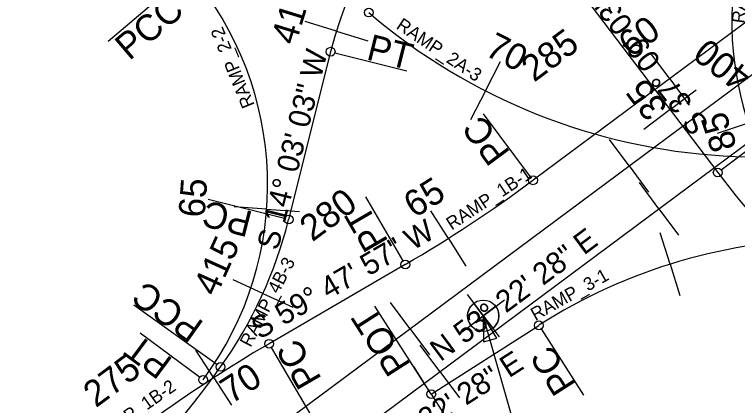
# Model space of a CAD drawing. Extents: x 1603447 to 1622636, y 1083818 to 1103958.
# Drawn here: x 1609242 to 1610566, y 1093148 to 1093865 of the extents above; entities that cross this region are included whole.
import ezdxf

# ---------------------------------------------------------------- set-up
doc = ezdxf.new("R2010")
doc.units = 0
for name, color, linetype in [('Level 1', 7, 'Continuous'), ('RD_HC_Points', 7, 'Continuous'), ('RD_HC_SUR_Bearing_TX400', 7, 'Continuous'), ('RD_HC_SUR_CL400', 7, 'Continuous'), ('RD_HC_SUR_PC_PT_400', 7, 'Continuous'), ('RD_HC_SUR_Tic400', 7, 'Continuous'), ('RD_HC_SUR_TX_Sta400', 7, 'Continuous'), ('RD_SHT_Misc1', 7, 'Continuous'), ('RD_TX_Misc1', 7, 'Continuous')]:
    doc.layers.add(name, color=color, linetype=linetype)

msp = doc.modelspace()

# ---------------------------------------------------------------- linework, layer by layer
at = {"layer": 'Level 1'}
for p, q in [((1609556.2, 1093936.7), (1609413.5, 1093815.2)), ((1609580.8, 1093200.1), (1609471.7, 1093281.1))]:
    msp.add_line(p, q, dxfattribs=at)
msp.add_circle((1609587.2, 1093195.4), 8, dxfattribs=at)
at = {"layer": 'RD_HC_Points'}
msp.add_lwpolyline([(1610156.3, 1093025.9), (1610177.4, 1093042.6), (1610100.4, 1093312.8)], dxfattribs=at)
msp.add_lwpolyline([(1610125.1, 1093271.6), (1610100.4, 1093312.8), (1610101.2, 1093264.8)], close=True, dxfattribs=at)
at = {"layer": 'RD_HC_SUR_CL400'}
for p, q in [((1609261, 1092765), (1614429, 1096606.7)), ((1611290.5, 1094378), (1610191.6, 1093561.1)), ((1610217, 1093988.4), (1610529.9, 1093575.5)), ((1609780.9, 1093032.2), (1610899.7, 1093863.9)), ((1609820.9, 1093796.8), (1609744, 1093489.3)), ((1609957.7, 1093406.8), (1609708.2, 1093261.6)), ((1610005.3, 1093169.1), (1610202.4, 1093295.3))]:
    msp.add_line(p, q, dxfattribs=at)
for centre, radius, start, end in [((1611155.6, 1093853.7), 600, 109.8521, 236.724), ((1610558.2, 1093612.3), 760, 18.4471, 165.9491), ((1608910.9, 1091669.6), 2932.1, 37.9336, 56.1301), ((1608910.9, 1091669.6), 2908.8, 39.6334, 56.1301), ((1609105.4, 1093553), 600, 323.4116, 40.4045), ((1610606.4, 1094704), 1100, 229.4294, 303.6278), ((1612124, 1094783.4), 2000, 217.1508, 224.9911), ((1608700.1, 1095567.5), 2500, 300.2008, 306.6256), ((1608967.9, 1093683.5), 800, 324.5024, 345.9491), ((1610741.6, 1092453.1), 1000, 90.0249, 122.6256), ((1610965.7, 1091100.9), 2500, 120.2008, 126.0872), ((1607990.9, 1094380.3), 2000, 306.4947, 324.5024)]:
    msp.add_arc(centre, radius, start, end, dxfattribs=at)
at = {"layer": 'RD_HC_SUR_PC_PT_400'}
for p, q in [((1609828.7, 1093794.8), (1609960.5, 1093761.9)), ((1610186.8, 1093567.5), (1610101, 1093682.9)), ((1610536.2, 1093580.4), (1610650.8, 1093667.2)), ((1609953.7, 1093413.7), (1609885.3, 1093531.1)), ((1609736.2, 1093491.2), (1609596.8, 1093526.1)), ((1609612.7, 1093223.6), (1609460.1, 1093332.5)), ((1610001, 1093175.8), (1609902.1, 1093330.3)), ((1610206.8, 1093288.6), (1610284.3, 1093167.5)), ((1609712.2, 1093254.7), (1609784.5, 1093130.4))]:
    msp.add_line(p, q, dxfattribs=at)
for centre in [(1609891, 1093868.4), (1609820.9, 1093796.8), (1610529.9, 1093575.5), (1610191.6, 1093561.1), (1609744, 1093489.3), (1609957.7, 1093406.8), (1610202.4, 1093295.3), (1609708.2, 1093261.6), (1609619.2, 1093219), (1610005.3, 1093169.1)]:
    msp.add_circle(centre, 8, dxfattribs=at)
at = {"layer": 'RD_HC_SUR_Tic400'}
for p, q in [((1610555.6, 1093862.4), (1610555.6, 1093862.4)), ((1609831.4, 1093834.5), (1609774, 1093852.1)), ((1610321.8, 1093850.1), (1610321.8, 1093850.1)), ((1609831.4, 1093834.5), (1609888.8, 1093817)), ((1609935.7, 1093832.1), (1609935.7, 1093832.1)), ((1610522.2, 1093806.9), (1610522.2, 1093806.9)), ((1609652, 1093800.5), (1609652, 1093800.5)), ((1610442, 1093747.3), (1610406.2, 1093795.4)), ((1610104.4, 1093725.2), (1610131.8, 1093778.6)), ((1610017.6, 1093774.8), (1610017.6, 1093774.8)), ((1610382.2, 1093770.4), (1610382.2, 1093770.4)), ((1610562.5, 1093762.8), (1610562.5, 1093762.8)), ((1610442, 1093747.3), (1610477.8, 1093699.1)), ((1609806.2, 1093737.8), (1609806.2, 1093737.8)), ((1610442.6, 1093690.7), (1610490.4, 1093726.9)), ((1610104.4, 1093725.2), (1610077, 1093671.8)), ((1609685.5, 1093706.4), (1609685.5, 1093706.4)), ((1610528, 1093706.8), (1610528, 1093706.8)), ((1610361.7, 1093687.6), (1610361.7, 1093687.6)), ((1610442.6, 1093690.7), (1610394.8, 1093654.4)), ((1610195.3, 1093683.7), (1610195.3, 1093683.7)), ((1610585.8, 1093665.7), (1610528.8, 1093646.9)), ((1610289.7, 1093650.6), (1610289.7, 1093650.6)), ((1610447.7, 1093647.2), (1610447.7, 1093647.2)), ((1609781.9, 1093640.8), (1609781.9, 1093640.8)), ((1610367.5, 1093587.5), (1610331.7, 1093635.7)), ((1610281.5, 1093627.9), (1610281.5, 1093627.9)), ((1610386.6, 1093626.2), (1610386.6, 1093626.2)), ((1609702.9, 1093608.1), (1609702.9, 1093608.1)), ((1610485.4, 1093610.7), (1610485.4, 1093610.7)), ((1610503, 1093611), (1610503, 1093611)), ((1610367.5, 1093587.5), (1610403.3, 1093539.4)), ((1610201.2, 1093568.3), (1610201.2, 1093568.3)), ((1610502.5, 1093568.6), (1610502.5, 1093568.6)), ((1610422.2, 1093508.9), (1610386.4, 1093557.1)), ((1609757.6, 1093543.7), (1609757.6, 1093543.7)), ((1610287.2, 1093527.9), (1610287.2, 1093527.9)), ((1610564, 1093531.7), (1610564, 1093531.7)), ((1609703.7, 1093508.2), (1609643.9, 1093512.7)), ((1609703.7, 1093508.2), (1609763.6, 1093503.7)), ((1610036.6, 1093454.7), (1610004.5, 1093505.4)), ((1610120, 1093509.9), (1610120, 1093509.9)), ((1610422.2, 1093508.9), (1610458, 1093460.7)), ((1610206.9, 1093468.2), (1610206.9, 1093468.2)), ((1610442.7, 1093407.4), (1610424.8, 1093464.6)), ((1610036.6, 1093454.7), (1610068.7, 1093404)), ((1610341.9, 1093449.2), (1610341.9, 1093449.2)), ((1609732.2, 1093447.1), (1609732.2, 1093447.1)), ((1610539.5, 1093432.5), (1610539.5, 1093432.5)), ((1609688, 1093409.6), (1609688, 1093409.6)), ((1610126.7, 1093408.5), (1610126.7, 1093408.5)), ((1609951.1, 1093403), (1609951.1, 1093403)), ((1610442.7, 1093407.4), (1610460.7, 1093350.1)), ((1610261.7, 1093389.6), (1610261.7, 1093389.6)), ((1609696.7, 1093353.6), (1609642.1, 1093378.4)), ((1610349, 1093372.8), (1610349, 1093372.8)), ((1609696.7, 1093353.6), (1609751.4, 1093328.9)), ((1609864.6, 1093352.7), (1609864.6, 1093352.7)), ((1610046.4, 1093348.9), (1610046.4, 1093348.9)), ((1609966.2, 1093289.2), (1609930.4, 1093337.4)), ((1610181.4, 1093329.9), (1610181.4, 1093329.9)), ((1610259.1, 1093329), (1610259.1, 1093329)), ((1609656.2, 1093314.9), (1609656.2, 1093314.9)), ((1609778.2, 1093302.4), (1609778.2, 1093302.4)), ((1609966.2, 1093289.2), (1610002, 1093241.1)), ((1610173.8, 1093276.9), (1610173.8, 1093276.9)), ((1609649.9, 1093265.3), (1609649.9, 1093265.3)), ((1610101.2, 1093270.3), (1610101.2, 1093270.3)), ((1609606.8, 1093199.3), (1609574.2, 1093249.7)), ((1609691.8, 1093252), (1609691.8, 1093252)), ((1610020.9, 1093210.6), (1609985.1, 1093258.8)), ((1609609, 1093226.8), (1609609, 1093226.8)), ((1609885.9, 1093229.6), (1609885.9, 1093229.6)), ((1610089.5, 1093223), (1610089.5, 1093223)), ((1610005.3, 1093169.1), (1609973, 1093219.6)), ((1610020.9, 1093210.6), (1610056.7, 1093162.5)), ((1609606.8, 1093199.3), (1609639.4, 1093149)), ((1609593, 1093183.1), (1609593, 1093183.1)), ((1609805.7, 1093169.9), (1609805.7, 1093169.9)), ((1610005.3, 1093169.1), (1610037.7, 1093118.6)), ((1609940.7, 1093151), (1609940.7, 1093151))]:
    msp.add_line(p, q, dxfattribs=at)
at = {"layer": 'RD_SHT_Misc1'}
for p, q in [((1610061.6, 1093283.3), (1610139.2, 1093342.3)), ((1610061.6, 1093283.3), (1610139.2, 1093342.3)), ((1610061.6, 1093283.3), (1610139.2, 1093342.3)), ((1610061.6, 1093283.3), (1610139.2, 1093342.3)), ((1610070.9, 1093351.6), (1610129.9, 1093274)), ((1610070.9, 1093351.6), (1610129.9, 1093274)), ((1610070.9, 1093351.6), (1610129.9, 1093274)), ((1610070.9, 1093351.6), (1610129.9, 1093274)), ((1610100.4, 1093312.8), (1610083, 1093335.7)), ((1610100.4, 1093312.8), (1610083, 1093335.7)), ((1610100.4, 1093312.8), (1610083, 1093335.7)), ((1610100.4, 1093312.8), (1610083, 1093335.7)), ((1610123.3, 1093330.2), (1610100.4, 1093312.8)), ((1610123.3, 1093330.2), (1610100.4, 1093312.8)), ((1610123.3, 1093330.2), (1610100.4, 1093312.8)), ((1610123.3, 1093330.2), (1610100.4, 1093312.8)), ((1610077.5, 1093295.4), (1610100.4, 1093312.8)), ((1610077.5, 1093295.4), (1610100.4, 1093312.8)), ((1610077.5, 1093295.4), (1610100.4, 1093312.8)), ((1610077.5, 1093295.4), (1610100.4, 1093312.8)), ((1610100.4, 1093312.8), (1610117.8, 1093289.9)), ((1610100.4, 1093312.8), (1610117.8, 1093289.9)), ((1610100.4, 1093312.8), (1610117.8, 1093289.9)), ((1610100.4, 1093312.8), (1610117.8, 1093289.9))]:
    msp.add_line(p, q, dxfattribs=at)
msp.add_circle((1610100.4, 1093312.8), 28.8, dxfattribs=at)
msp.add_circle((1610100.4, 1093312.8), 28.8, dxfattribs=at)
msp.add_circle((1610100.4, 1093312.8), 28.8, dxfattribs=at)
msp.add_circle((1610100.4, 1093312.8), 28.8, dxfattribs=at)
for start, end in [(127.2464, 217.2464), (127.2464, 217.2464), (127.2464, 217.2464), (127.2464, 217.2464), (307.2464, 37.2464), (307.2464, 37.2464), (307.2464, 37.2464), (307.2464, 37.2464)]:
    msp.add_arc((1610100.4, 1093312.8), 28.8, start, end, dxfattribs=at)

# ---------------------------------------------------------------- texts
at = {"layer": 'Level 1'}
for s, rotation, p in [('PCC', 40.4045, (1609452.1, 1093779.4)), ('285', 36.6256, (1610193.5, 1093739.8)), ('35', 127.1508, (1610440.2, 1093694.6)), ('85', 108.2612, (1610565.8, 1093622.6)), ('65', 32.3173, (1609974.6, 1093490.8)), ('65', 85.7181, (1609589.8, 1093491.9)), ('415', 65.6451, (1609611.4, 1093346.4)), ('PT', 143.4116, (1609533.8, 1093232.5)), ('275', 36.6256, (1609390.9, 1093143.2))]:
    msp.add_text(s, height=48, rotation=rotation, dxfattribs=at).set_placement(p)
at = {"layer": 'RD_HC_SUR_Bearing_TX400'}
for s, rotation, p in [('S 37%%d 09\' 03" E', 127.1508, (1610515.9, 1093663.2)), ('S 14%%d 03\' 03" W', 75.9491, (1609724.3, 1093431.2)), ('S 59%%d 47\' 57" W', 30.2008, (1609690.7, 1093268.6)), ('N 53%%d 22\' 28" E', 36.6256, (1610022.2, 1093227.7)), ('N 57%%d 22\' 28" E', 32.6256, (1609871.9, 1093021.6))]:
    msp.add_text(s, height=40, rotation=rotation, dxfattribs=at).set_placement(p)
at = {"layer": 'RD_HC_SUR_PC_PT_400'}
for s, rotation, p in [('PT', 345.9491, (1609884.5, 1093782.9)), ('PC', 126.6256, (1610151.2, 1093612.1)), ('PC', 165.9491, (1609680.4, 1093503.1)), ('PT', 120.2008, (1609927.5, 1093449)), ('PCC', 144.5024, (1609590.9, 1093299.9)), ('POT', 122.6256, (1609968.6, 1093222.8)), ('PC', 120.2008, (1609805.4, 1093197.1)), ('PC', 122.6256, (1610272.8, 1093187.2))]:
    msp.add_text(s, height=48, rotation=rotation, dxfattribs=at).set_placement(p)
at = {"layer": 'RD_HC_SUR_TX_Sta400'}
for s, rotation, p in [('410', 72.9965, (1609756.6, 1093807.1)), ('60', 36.6256, (1610371.2, 1093784.8)), ('70', 332.848, (1610101.4, 1093791.5)), ('400', 142.1517, (1610595.7, 1093758)), ('280', 36.6256, (1609787.3, 1093447.3)), ('70', 32.9267, (1609638.9, 1093150.3))]:
    msp.add_text(s, height=48, rotation=rotation, dxfattribs=at).set_placement(p)
at = {"layer": 'RD_TX_Misc1'}
for s, rotation, p in [('RAMP_1A-4', 82.2275, (1610578.7, 1093847.6)), ('RAMP_2A-3', 326.0791, (1609939.3, 1093840.3)), ('RAMP_2-2', 112.2835, (1609682.1, 1093699.3)), ('RAMP_1B-1', 33.2938, (1610042.6, 1093468.9)), ('RAMP_4B-3', 62.5523, (1609674.4, 1093253.7)), ('RAMP_3-1', 29.369, (1610195.9, 1093302.9)), ('RAMP_1B-2', 34.9418, (1609393.7, 1093075.8))]:
    msp.add_text(s, height=24, rotation=rotation, dxfattribs=at).set_placement(p)

doc.saveas('drawing.dxf')
